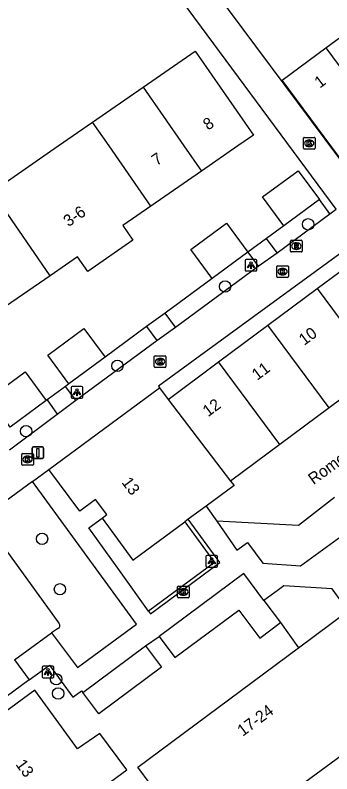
# Model space of a CAD drawing. Extents: x 161801 to 162379, y 382315 to 382832.
# Drawn here: x 162004.5 to 162031.7, y 382446.1 to 382511.2 of the extents above; entities that cross this region are included whole.
import ezdxf

# ---------------------------------------------------------------- set-up
doc = ezdxf.new("R2010")
doc.units = 0
for name, color, linetype in [('IMGEO_Afsluitpaal', 7, 'Continuous'), ('IMGEO_Boom', 7, 'Continuous'), ('IMGEO_Groenvoorziening', 7, 'Continuous'), ('IMGEO_Haag', 7, 'Continuous'), ('IMGEO_Kolk', 7, 'Continuous'), ('IMGEO_Lichtpunt', 7, 'Continuous'), ('IMGEO_Openbare_ruimte_label', 7, 'Continuous'), ('IMGEO_Pand', 7, 'Continuous'), ('IMGEO_Pand_nummerreeks', 7, 'Continuous'), ('IMGEO_Parkeervlak_open', 7, 'Continuous'), ('IMGEO_Rijbaan_lokaal_open', 7, 'Continuous'), ('IMGEO_Rioolput', 7, 'Continuous'), ('IMGEO_Voetpad_open', 7, 'Continuous')]:
    doc.layers.add(name, color=color, linetype=linetype)

msp = doc.modelspace()

# ---------------------------------------------------------------- linework, layer by layer
at = {"layer": 'IMGEO_Afsluitpaal'}
for p, q in [((162005.998, 382473.265), (162005.998, 382474.065)), ((162005.998, 382474.065), (162005.998, 382473.265)), ((162006.098, 382474.165), (162006.888, 382474.165)), ((162006.888, 382474.165), (162006.098, 382474.165)), ((162006.988, 382474.065), (162006.988, 382473.265)), ((162006.988, 382473.265), (162006.988, 382474.065)), ((162006.888, 382473.165), (162006.098, 382473.165)), ((162006.098, 382473.165), (162006.888, 382473.165))]:
    msp.add_line(p, q, dxfattribs=at)
msp.add_lwpolyline([(162006.418, 382474.04), (162006.568, 382474.04), (162006.568, 382473.29), (162006.418, 382473.29), (162006.418, 382474.04)], dxfattribs=at)
for centre, start, end in [((162006.098, 382474.065), 90, 180), ((162006.098, 382474.065), 90, 180), ((162006.888, 382474.065), 0, 90), ((162006.888, 382474.065), 360, 90), ((162006.098, 382473.265), 180, 270), ((162006.098, 382473.265), 180, 270), ((162006.888, 382473.265), 270, 0), ((162006.888, 382473.265), 270, 0)]:
    msp.add_arc(centre, 0.1, start, end, dxfattribs=at)
at = {"layer": 'IMGEO_Boom'}
for centre in [(162029.678, 382493.268), (162022.556, 382487.933), (162013.318, 382481.122), (162005.484, 382475.507), (162006.853, 382466.276), (162008.388, 382461.945), (162008.07, 382454.219), (162008.233, 382453)]:
    msp.add_circle(centre, 0.489, dxfattribs=at)
at = {"layer": 'IMGEO_Groenvoorziening'}
for points in [[(162031.539, 382494.162), (162030.66, 382495.383)], [(162027.591, 382493.128), (162026.119, 382492.053)], [(162021.437, 382488.62), (162017.402, 382485.647)], [(162015.826, 382484.485), (162012.263, 382481.86)], [(162009.152, 382479.575), (162008.857, 382479.357)], [(162007.284, 382478.193), (162007.212, 382478.139)], [(162031.951, 382469.817), (162028.852, 382467.407), (162021.844, 382467.777)], [(162027.309, 382459.079), (162028.864, 382456.929)]]:
    msp.add_lwpolyline(points, dxfattribs=at)
at = {"layer": 'IMGEO_Haag'}
msp.add_lwpolyline([(162019.117, 382467.74), (162021.647, 382464.242), (162015.992, 382460.062)], dxfattribs=at)
at = {"layer": 'IMGEO_Kolk'}
for p, q in [((162029.276, 382499.802), (162029.276, 382500.654)), ((162029.351, 382500.728), (162030.203, 382500.728)), ((162029.764, 382500.508), (162029.789, 382500.508)), ((162030.277, 382500.654), (162030.277, 382499.802)), ((162029.787, 382499.948), (162029.762, 382499.948)), ((162030.203, 382499.728), (162029.351, 382499.728)), ((162026.986, 382488.783), (162026.986, 382489.635)), ((162027.061, 382489.709), (162027.913, 382489.709)), ((162027.474, 382489.489), (162027.499, 382489.489)), ((162027.987, 382489.635), (162027.987, 382488.783)), ((162027.497, 382488.929), (162027.472, 382488.929)), ((162027.913, 382488.709), (162027.061, 382488.709)), ((162016.481, 382481.058), (162016.481, 382481.91)), ((162016.556, 382481.984), (162017.408, 382481.984)), ((162016.969, 382481.764), (162016.994, 382481.764)), ((162017.482, 382481.91), (162017.482, 382481.058)), ((162017.408, 382480.984), (162016.556, 382480.984)), ((162016.992, 382481.204), (162016.967, 382481.204)), ((162005.109, 382472.663), (162005.109, 382473.515)), ((162005.184, 382473.589), (162006.036, 382473.589)), ((162005.597, 382473.369), (162005.622, 382473.369)), ((162006.11, 382473.515), (162006.11, 382472.663)), ((162006.036, 382472.589), (162005.184, 382472.589)), ((162005.62, 382472.809), (162005.595, 382472.809)), ((162018.475, 382461.292), (162018.475, 382462.144)), ((162018.55, 382462.218), (162019.402, 382462.218)), ((162019.476, 382462.144), (162019.476, 382461.292)), ((162018.986, 382461.438), (162018.961, 382461.438)), ((162018.963, 382461.998), (162018.988, 382461.998)), ((162019.402, 382461.218), (162018.55, 382461.218))]:
    msp.add_line(p, q, dxfattribs=at)
for points in [[(162029.276, 382499.802), (162029.276, 382500.654)], [(162029.351, 382500.728), (162030.203, 382500.728)], [(162030.277, 382500.654), (162030.277, 382499.802)], [(162029.597, 382500.428), (162029.72, 382500.428), (162029.72, 382500.277), (162029.85, 382500.428), (162030.014, 382500.428), (162029.868, 382500.277), (162030.021, 382500.028), (162029.869, 382500.028), (162029.784, 382500.192), (162029.72, 382500.125), (162029.72, 382500.028), (162029.597, 382500.028), (162029.597, 382500.428)], [(162030.203, 382499.728), (162029.351, 382499.728)], [(162026.986, 382488.783), (162026.986, 382489.635)], [(162027.061, 382489.709), (162027.913, 382489.709)], [(162027.987, 382489.635), (162027.987, 382488.783)], [(162027.307, 382489.409), (162027.43, 382489.409), (162027.43, 382489.258), (162027.56, 382489.409), (162027.724, 382489.409), (162027.578, 382489.258), (162027.731, 382489.009), (162027.579, 382489.009), (162027.494, 382489.173), (162027.43, 382489.106), (162027.43, 382489.009), (162027.307, 382489.009), (162027.307, 382489.409)], [(162027.913, 382488.709), (162027.061, 382488.709)], [(162016.481, 382481.058), (162016.481, 382481.91)], [(162016.556, 382481.984), (162017.408, 382481.984)], [(162016.802, 382481.684), (162016.925, 382481.684), (162016.925, 382481.533), (162017.055, 382481.684), (162017.219, 382481.684), (162017.073, 382481.533), (162017.226, 382481.284), (162017.074, 382481.284), (162016.989, 382481.448), (162016.925, 382481.381), (162016.925, 382481.284), (162016.802, 382481.284), (162016.802, 382481.684)], [(162017.482, 382481.91), (162017.482, 382481.058)], [(162017.408, 382480.984), (162016.556, 382480.984)], [(162005.109, 382472.663), (162005.109, 382473.515)], [(162005.184, 382473.589), (162006.036, 382473.589)], [(162005.43, 382473.289), (162005.553, 382473.289), (162005.553, 382473.138), (162005.683, 382473.289), (162005.847, 382473.289), (162005.701, 382473.138), (162005.854, 382472.889), (162005.702, 382472.889), (162005.617, 382473.053), (162005.553, 382472.986), (162005.553, 382472.889), (162005.43, 382472.889), (162005.43, 382473.289)], [(162006.11, 382473.515), (162006.11, 382472.663)], [(162006.036, 382472.589), (162005.184, 382472.589)], [(162018.475, 382461.292), (162018.475, 382462.144)], [(162018.55, 382462.218), (162019.402, 382462.218)], [(162019.476, 382462.144), (162019.476, 382461.292)], [(162018.796, 382461.918), (162018.919, 382461.918), (162018.919, 382461.767), (162019.049, 382461.918), (162019.213, 382461.918), (162019.067, 382461.767), (162019.22, 382461.518), (162019.068, 382461.518), (162018.983, 382461.682), (162018.919, 382461.615), (162018.919, 382461.518), (162018.796, 382461.518), (162018.796, 382461.918)], [(162019.402, 382461.218), (162018.55, 382461.218)]]:
    msp.add_lwpolyline(points, dxfattribs=at)
for centre, start, end in [((162029.353, 382500.652), 91.55205, 178.44795), ((162029.353, 382500.652), 91.55205, 178.44795), ((162030.201, 382500.652), 1.55205, 88.44795), ((162030.201, 382500.652), 1.55205, 88.44795), ((162029.353, 382499.804), 181.55205, 268.44795), ((162029.353, 382499.804), 181.55205, 268.44795), ((162030.201, 382499.804), 271.55205, 358.44795), ((162030.201, 382499.804), 271.55205, 358.44795), ((162027.063, 382489.633), 91.55205, 178.44795), ((162027.063, 382489.633), 91.55205, 178.44795), ((162027.911, 382489.633), 1.55205, 88.44795), ((162027.911, 382489.633), 1.55205, 88.44795), ((162027.063, 382488.785), 181.55205, 268.44795), ((162027.063, 382488.785), 181.55205, 268.44795), ((162027.911, 382488.785), 271.55205, 358.44795), ((162027.911, 382488.785), 271.55205, 358.44795), ((162016.558, 382481.908), 91.55205, 178.44795), ((162016.558, 382481.908), 91.55205, 178.44795), ((162017.406, 382481.908), 1.55205, 88.44795), ((162017.406, 382481.908), 1.55205, 88.44795), ((162016.558, 382481.06), 181.55205, 268.44795), ((162016.558, 382481.06), 181.55205, 268.44795), ((162017.406, 382481.06), 271.55205, 358.44795), ((162017.406, 382481.06), 271.55205, 358.44795), ((162005.186, 382473.513), 91.55205, 178.44795), ((162005.186, 382473.513), 91.55205, 178.44795), ((162006.034, 382473.513), 1.55205, 88.44795), ((162006.034, 382473.513), 1.55205, 88.44795), ((162005.186, 382472.665), 181.55205, 268.44795), ((162005.186, 382472.665), 181.55205, 268.44795), ((162006.034, 382472.665), 271.55205, 358.44795), ((162006.034, 382472.665), 271.55205, 358.44795), ((162018.552, 382462.142), 91.55205, 178.44795), ((162018.552, 382462.142), 91.55205, 178.44795), ((162019.4, 382462.142), 1.55205, 88.44795), ((162019.4, 382462.142), 1.55205, 88.44795), ((162018.552, 382461.294), 181.55205, 268.44795), ((162018.552, 382461.294), 181.55205, 268.44795), ((162019.4, 382461.294), 271.55205, 358.44795), ((162019.4, 382461.294), 271.55205, 358.44795)]:
    msp.add_arc(centre, 0.0765, start, end, dxfattribs=at)
for centre, major_axis, ratio, start_param, end_param in [((162029.763, 382500.228), (-0.387, 0.002), 0.722429, 4.712389, 7.853982), ((162029.788, 382500.228), (-0.39, 0.002), 0.717154, 1.570796, 4.712389), ((162027.473, 382489.209), (-0.387, 0.002), 0.722429, 4.712389, 7.853982), ((162027.498, 382489.209), (-0.39, 0.002), 0.717154, 1.570796, 4.712389), ((162016.968, 382481.484), (-0.387, 0.002), 0.722429, 4.712389, 7.853982), ((162016.993, 382481.484), (-0.39, 0.002), 0.717154, 1.570796, 4.712389), ((162005.596, 382473.089), (-0.387, 0.002), 0.722429, 4.712389, 7.853982), ((162005.621, 382473.089), (-0.39, 0.002), 0.717154, 1.570796, 4.712389), ((162018.962, 382461.718), (-0.387, 0.002), 0.722429, 4.712389, 7.853982), ((162018.987, 382461.718), (-0.39, 0.002), 0.717154, 1.570796, 4.712389)]:
    msp.add_ellipse(centre, major_axis=major_axis, ratio=ratio, start_param=start_param, end_param=end_param, dxfattribs=at)
at = {"layer": 'IMGEO_Lichtpunt'}
for p, q in [((162024.281, 382490.162), (162024.281, 382489.355)), ((162024.281, 382490.162), (162024.281, 382489.355)), ((162025.183, 382490.257), (162024.375, 382490.257)), ((162025.183, 382490.257), (162024.375, 382490.257)), ((162025.277, 382489.355), (162025.277, 382490.162)), ((162025.277, 382489.355), (162025.277, 382490.162)), ((162024.375, 382489.261), (162025.183, 382489.261)), ((162024.375, 382489.261), (162025.183, 382489.261)), ((162009.348, 382479.251), (162009.348, 382478.444)), ((162009.348, 382479.251), (162009.348, 382478.444)), ((162010.25, 382479.346), (162009.442, 382479.346)), ((162010.25, 382479.346), (162009.442, 382479.346)), ((162010.344, 382478.444), (162010.344, 382479.251)), ((162010.344, 382478.444), (162010.344, 382479.251)), ((162009.442, 382478.35), (162010.25, 382478.35)), ((162009.442, 382478.35), (162010.25, 382478.35)), ((162020.916, 382464.753), (162020.916, 382463.946)), ((162020.916, 382464.753), (162020.916, 382463.946)), ((162021.818, 382464.848), (162021.01, 382464.848)), ((162021.818, 382464.848), (162021.01, 382464.848)), ((162021.912, 382463.946), (162021.912, 382464.753)), ((162021.912, 382463.946), (162021.912, 382464.753)), ((162021.01, 382463.852), (162021.818, 382463.852)), ((162021.01, 382463.852), (162021.818, 382463.852)), ((162006.863, 382455.241), (162006.863, 382454.434)), ((162006.863, 382455.241), (162006.863, 382454.434)), ((162007.765, 382455.336), (162006.957, 382455.336)), ((162007.765, 382455.336), (162006.957, 382455.336)), ((162007.859, 382454.434), (162007.859, 382455.241)), ((162007.859, 382454.434), (162007.859, 382455.241)), ((162006.957, 382454.34), (162007.765, 382454.34)), ((162006.957, 382454.34), (162007.765, 382454.34))]:
    msp.add_line(p, q, dxfattribs=at)
for points in [[(162024.655, 382489.826), (162024.694, 382489.798), (162024.506, 382489.536), (162024.468, 382489.563), (162024.655, 382489.826)], [(162024.757, 382489.778), (162024.804, 382489.778), (162024.804, 382489.456), (162024.757, 382489.456), (162024.757, 382489.778)], [(162024.867, 382489.798), (162024.905, 382489.825), (162025.092, 382489.563), (162025.053, 382489.535), (162024.867, 382489.798)], [(162009.722, 382478.915), (162009.761, 382478.887), (162009.573, 382478.625), (162009.535, 382478.652), (162009.722, 382478.915)], [(162009.824, 382478.867), (162009.871, 382478.867), (162009.871, 382478.545), (162009.824, 382478.545), (162009.824, 382478.867)], [(162009.934, 382478.887), (162009.972, 382478.914), (162010.159, 382478.652), (162010.12, 382478.624), (162009.934, 382478.887)], [(162021.29, 382464.417), (162021.329, 382464.389), (162021.141, 382464.127), (162021.103, 382464.154), (162021.29, 382464.417)], [(162021.392, 382464.369), (162021.439, 382464.369), (162021.439, 382464.047), (162021.392, 382464.047), (162021.392, 382464.369)], [(162021.502, 382464.389), (162021.54, 382464.416), (162021.727, 382464.154), (162021.688, 382464.126), (162021.502, 382464.389)], [(162007.237, 382454.905), (162007.276, 382454.877), (162007.088, 382454.615), (162007.05, 382454.642), (162007.237, 382454.905)], [(162007.339, 382454.857), (162007.386, 382454.857), (162007.386, 382454.535), (162007.339, 382454.535), (162007.339, 382454.857)], [(162007.449, 382454.877), (162007.487, 382454.904), (162007.674, 382454.642), (162007.635, 382454.614), (162007.449, 382454.877)]]:
    msp.add_lwpolyline(points, dxfattribs=at)
for centre in [(162024.78, 382489.96), (162009.847, 382479.049), (162021.415, 382464.551), (162007.362, 382455.039)]:
    msp.add_circle(centre, 0.0994, dxfattribs=at)
for centre, start, end in [((162024.375, 382490.162), 90, 180), ((162024.375, 382490.162), 90, 180), ((162025.183, 382490.162), 0, 90), ((162025.183, 382490.162), 0, 90), ((162024.375, 382489.355), 180, 270), ((162024.375, 382489.355), 180, 270), ((162025.183, 382489.355), 270, 0), ((162025.183, 382489.355), 270, 360), ((162009.442, 382479.251), 90, 180), ((162009.442, 382479.251), 90, 180), ((162010.25, 382479.251), 0, 90), ((162010.25, 382479.251), 0, 90), ((162009.442, 382478.444), 180, 270), ((162009.442, 382478.444), 180, 270), ((162010.25, 382478.444), 270, 0), ((162010.25, 382478.444), 270, 360), ((162021.01, 382464.753), 90, 180), ((162021.01, 382464.753), 90, 180), ((162021.818, 382464.753), 0, 90), ((162021.818, 382464.753), 0, 90), ((162021.01, 382463.946), 180, 270), ((162021.01, 382463.946), 180, 270), ((162021.818, 382463.946), 270, 0), ((162021.818, 382463.946), 270, 360), ((162006.957, 382455.241), 90, 180), ((162006.957, 382455.241), 90, 180), ((162007.765, 382455.241), 0, 90), ((162007.765, 382455.241), 0, 90), ((162006.957, 382454.434), 180, 270), ((162006.957, 382454.434), 180, 270), ((162007.765, 382454.434), 270, 0), ((162007.765, 382454.434), 270, 360)]:
    msp.add_arc(centre, 0.0946, start, end, dxfattribs=at)
at = {"layer": 'IMGEO_Pand'}
for points in [[(162031.195, 382508.4), (162034.935, 382511.174)], [(162033.521, 382497.469), (162027.455, 382505.625), (162031.195, 382508.4)], [(162031.195, 382508.4), (162037.25, 382500.238)], [(162015.531, 382505.046), (162019.993, 382508.136), (162022.139, 382505.038), (162024.987, 382500.927), (162023.649, 382500), (162020.522, 382497.834)], [(162011.191, 382502.039), (162015.531, 382505.046)], [(162015.531, 382505.046), (162019.023, 382500), (162020.522, 382497.834)], [(162002.559, 382496.061), (162008.247, 382500), (162011.191, 382502.039)], [(162016.181, 382494.828), (162012.602, 382500), (162011.191, 382502.039)], [(162020.522, 382497.834), (162016.181, 382494.828)], [(162027.591, 382493.128), (162025.765, 382495.613), (162028.834, 382497.868), (162030.66, 382495.383)], [(162007.543, 382488.859), (162003.194, 382495.144), (162002.559, 382496.061)], [(162030.66, 382495.383), (162027.591, 382493.128)], [(162016.181, 382494.828), (162013.781, 382493.165), (162014.653, 382491.905), (162010.774, 382489.218), (162009.894, 382490.488), (162007.543, 382488.859)], [(162021.437, 382488.62), (162019.613, 382491.103), (162022.673, 382493.352), (162024.497, 382490.869)], [(162024.497, 382490.869), (162021.437, 382488.62)], [(162030.464, 382487.747), (162034.162, 382490.494), (162039.422, 382483.414), (162035.723, 382480.666)], [(162007.543, 382488.859), (162003.252, 382485.887)], [(162026.232, 382484.603), (162030.464, 382487.747)], [(162030.464, 382487.747), (162035.723, 382480.666)], [(162009.152, 382479.575), (162007.34, 382482.041), (162010.451, 382484.326), (162012.263, 382481.86)], [(162022, 382481.459), (162026.232, 382484.603)], [(162031.491, 382477.523), (162026.232, 382484.603)], [(162012.263, 382481.86), (162009.152, 382479.575)], [(162017.674, 382478.245), (162022, 382481.459)], [(162027.259, 382474.379), (162022, 382481.459)], [(162004.124, 382475.871), (162002.31, 382478.34), (162005.398, 382480.608), (162007.212, 382478.139)], [(162035.723, 382480.666), (162031.491, 382477.523)], [(162007.424, 382472.237), (162016.933, 382479.242)], [(162016.933, 382479.242), (162017.674, 382478.245)], [(162007.212, 382478.139), (162004.124, 382475.871)], [(162017.674, 382478.245), (162023.027, 382471.235)], [(162031.491, 382477.523), (162027.259, 382474.379)], [(162027.259, 382474.379), (162023.027, 382471.235)], [(162012.001, 382468.042), (162012.419, 382468.351), (162011.452, 382469.65), (162010.085, 382468.639), (162007.424, 382472.237)], [(162023.027, 382471.235), (162023.322, 382470.839), (162020.939, 382469.083)], [(162020.939, 382469.083), (162019.403, 382467.951)], [(162012.001, 382468.042), (162014.651, 382464.45), (162019.117, 382467.74)], [(162019.403, 382467.951), (162019.117, 382467.74)], [(162025.891, 382460.987), (162024.164, 382463.31), (162016.893, 382457.905)], [(162025.891, 382460.987), (162027.309, 382459.079)], [(162016.893, 382457.905), (162018.249, 382456.081), (162023.736, 382460.159), (162025.524, 382457.753), (162027.309, 382459.079)], [(162028.864, 382456.929), (162033.12, 382460.093)], [(162010.363, 382453.084), (162015.74, 382457.081)], [(162015.74, 382457.081), (162017.098, 382455.255), (162011.721, 382451.258), (162010.363, 382453.084)], [(162016.135, 382445.239), (162015.069, 382446.675), (162028.864, 382456.929)], [(162012.297, 382445.1), (162014.128, 382446.461), (162011.818, 382449.569), (162009.909, 382448.237), (162006.221, 382453.297), (162000.03, 382448.734), (162004.978, 382441.988), (162005.81, 382440.854), (162006.084, 382440.48)], [(162039.058, 382452.455), (162020.713, 382438.983), (162019.568, 382440.542)]]:
    msp.add_lwpolyline(points, dxfattribs=at)
at = {"layer": 'IMGEO_Parkeervlak_open'}
for points in [[(162002.74, 382466.671), (162008.289, 382459.041)], [(162008.275, 382458.597), (162007.669, 382458.194)]]:
    msp.add_lwpolyline(points, dxfattribs=at)
msp.add_arc((162008.086, 382458.825), 0.296, 309.66561, 46.72234, dxfattribs=at)
at = {"layer": 'IMGEO_Rijbaan_lokaal_open'}
for points in [[(162004.499, 382455.882), (162005.757, 382454.164)], [(162005.757, 382454.164), (161994.889, 382446.161), (161994.794, 382444.891), (161994.413, 382444.586)]]:
    msp.add_lwpolyline(points, dxfattribs=at)
at = {"layer": 'IMGEO_Rioolput'}
for p, q in [((162028.168, 382490.968), (162028.168, 382491.82)), ((162028.243, 382491.894), (162029.095, 382491.894)), ((162028.656, 382491.674), (162028.681, 382491.674)), ((162029.169, 382491.82), (162029.169, 382490.968)), ((162029.095, 382490.894), (162028.243, 382490.894)), ((162028.679, 382491.114), (162028.654, 382491.114))]:
    msp.add_line(p, q, dxfattribs=at)
for points in [[(162028.168, 382490.968), (162028.168, 382491.82)], [(162028.243, 382491.894), (162029.095, 382491.894)], [(162028.757, 382491.592), (162028.505, 382491.594), (162028.505, 382491.194)], [(162028.683, 382491.513), (162028.629, 382491.513), (162028.629, 382491.432)], [(162028.629, 382491.432), (162028.681, 382491.432)], [(162029.169, 382491.82), (162029.169, 382490.968)], [(162029.095, 382490.894), (162028.243, 382490.894)], [(162028.505, 382491.194), (162028.629, 382491.194), (162028.629, 382491.356), (162028.64, 382491.356)], [(162028.687, 382491.327), (162028.758, 382491.194), (162028.898, 382491.194), (162028.833, 382491.32)]]:
    msp.add_lwpolyline(points, dxfattribs=at)
for centre, radius, start, end in [((162028.245, 382491.818), 0.0765, 91.55205, 178.44795), ((162028.245, 382491.818), 0.0765, 91.55205, 178.44795), ((162028.665, 382491.621), 0.19, 274.7715, 282.96867), ((162028.689, 382491.417), 0.0964, 77.00612, 93.18647), ((162028.703, 382491.474), 0.0378, 276.66336, 79.67722), ((162028.756, 382491.482), 0.109, 350.36119, 89.41601), ((162028.754, 382491.482), 0.112, 277.58423, 350.98172), ((162029.093, 382491.818), 0.0765, 1.55205, 88.44795), ((162029.093, 382491.818), 0.0765, 1.55205, 88.44795), ((162028.245, 382490.97), 0.0765, 181.55205, 268.44795), ((162028.245, 382490.97), 0.0765, 181.55205, 268.44795), ((162028.639, 382491.303), 0.0533, 26.02933, 88.69889), ((162028.738, 382491.267), 0.108, 29.51342, 73.79051), ((162029.093, 382490.97), 0.0765, 271.55205, 358.44795), ((162029.093, 382490.97), 0.0765, 271.55205, 358.44795)]:
    msp.add_arc(centre, radius, start, end, dxfattribs=at)
for centre, major_axis, ratio, start_param, end_param in [((162028.655, 382491.394), (-0.387, 0.002), 0.722429, 4.712389, 7.853982), ((162028.68, 382491.394), (-0.39, 0.002), 0.717154, 1.570796, 4.712389)]:
    msp.add_ellipse(centre, major_axis=major_axis, ratio=ratio, start_param=start_param, end_param=end_param, dxfattribs=at)
at = {"layer": 'IMGEO_Voetpad_open'}
for points in [[(162012.842, 382526.959), (162012.729, 382526.884), (162018.127, 382518.324), (162019.294, 382516.448), (162033.46, 382497.424)], [(162031.539, 382494.162), (162032.099, 382494.574), (162017.357, 382514.511), (162016.252, 382513.875)], [(162027.016, 382490.833), (162031.539, 382494.162)], [(162026.119, 382492.053), (162024.497, 382490.869)], [(162027.016, 382490.833), (162026.119, 382492.053)], [(162045.442, 382476.242), (162034.7, 382490.915), (162033.984, 382491.893), (162033.451, 382491.503), (162022.878, 382483.771), (162016.83, 382479.386), (162016.933, 382479.242)], [(162024.497, 382490.869), (162025.399, 382489.685)], [(162025.399, 382489.685), (162027.016, 382490.833)], [(162018.29, 382484.454), (162025.399, 382489.685)], [(162017.402, 382485.647), (162015.826, 382484.485)], [(162018.29, 382484.454), (162017.402, 382485.647)], [(162015.826, 382484.485), (162016.708, 382483.289)], [(162016.708, 382483.289), (162018.29, 382484.454)], [(162009.756, 382478.166), (162016.708, 382483.289)], [(162008.857, 382479.357), (162007.284, 382478.193)], [(162009.756, 382478.166), (162008.857, 382479.357)], [(162007.284, 382478.193), (162008.16, 382476.967)], [(162008.16, 382476.967), (162009.756, 382478.166)], [(162004.068, 382473.92), (162008.16, 382476.967)], [(162006.029, 382471.189), (162007.424, 382472.237)], [(162006.029, 382471.189), (161997.4, 382464.883)], [(162007.669, 382458.194), (162009.907, 382455.239), (162014.95, 382458.955), (162006.029, 382471.189)], [(162020.939, 382469.083), (162021.844, 382467.777)], [(162015.992, 382460.062), (162013.486, 382463.56), (162010.872, 382467.208), (162012.001, 382468.042)], [(162015.992, 382460.062), (162016.159, 382459.829), (162022.113, 382464.234), (162019.403, 382467.951)], [(162021.844, 382467.777), (162023.567, 382465.307), (162024.49, 382465.967), (162025.798, 382464.194), (162029.013, 382463.958), (162033.734, 382467.382)], [(162033.12, 382460.093), (162031.744, 382461.98), (162027.597, 382462.232), (162027.134, 382461.905), (162025.891, 382460.987)], [(162004.499, 382455.882), (162007.669, 382458.194)], [(162015.74, 382457.081), (162016.893, 382457.905)], [(162005.757, 382454.164), (162007.481, 382455.433), (162009.495, 382452.688), (162010.225, 382453.214), (162010.363, 382453.084)]]:
    msp.add_lwpolyline(points, dxfattribs=at)

# ---------------------------------------------------------------- texts
at = {"layer": 'IMGEO_Openbare_ruimte_label'}
msp.add_text('Romerohof', height=1, rotation=35.80411, dxfattribs=at).set_placement((162030.141, 382470.882))
at = {"layer": 'IMGEO_Pand_nummerreeks'}
for s, rotation, p in [('1', 36.5719, (162030.685, 382504.909)), ('8', 34.71025, (162021.096, 382501.297)), ('7', 34.70813, (162016.69, 382498.246)), ('3-6', 34.55508, (162009.113, 382493.01)), ('10', 36.6088, (162029.347, 382482.831)), ('11', 36.6088, (162025.314, 382479.834)), ('12', 36.6088, (162021.098, 382476.702)), ('13', 306.58887, (162013.637, 382471.115)), ('17-24', 36.62346, (162024.071, 382449.28)), ('13', 306.36542, (162004.545, 382446.903))]:
    msp.add_text(s, height=1, rotation=rotation, dxfattribs=at).set_placement(p)

doc.saveas('drawing.dxf')
